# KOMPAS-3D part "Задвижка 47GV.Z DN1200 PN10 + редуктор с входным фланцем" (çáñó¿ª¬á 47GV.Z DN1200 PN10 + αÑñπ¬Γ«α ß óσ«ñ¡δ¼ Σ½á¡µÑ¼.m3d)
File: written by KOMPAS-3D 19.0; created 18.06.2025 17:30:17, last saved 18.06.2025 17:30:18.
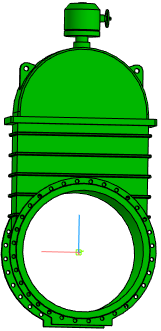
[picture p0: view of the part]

Document properties: Полное имя файла: Задвижка 47GV.Z DN1200 PN10 + редуктор с входным валом.a3d

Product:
- Part/product: Задвижка 47GV.Z DN1200 PN10 + редуктор с входным фланцем
    Масса: 6460.63
  - Body: Тело 1
      Масса: 6462.73

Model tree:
1. Операция без истории:1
